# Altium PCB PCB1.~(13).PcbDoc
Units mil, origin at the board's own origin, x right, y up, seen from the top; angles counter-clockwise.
Board outline 6000 x 4000 mil, 2 copper layers (Top Layer, Bottom Layer); 3 components, 4 nets, 37 pads, 0 vias.
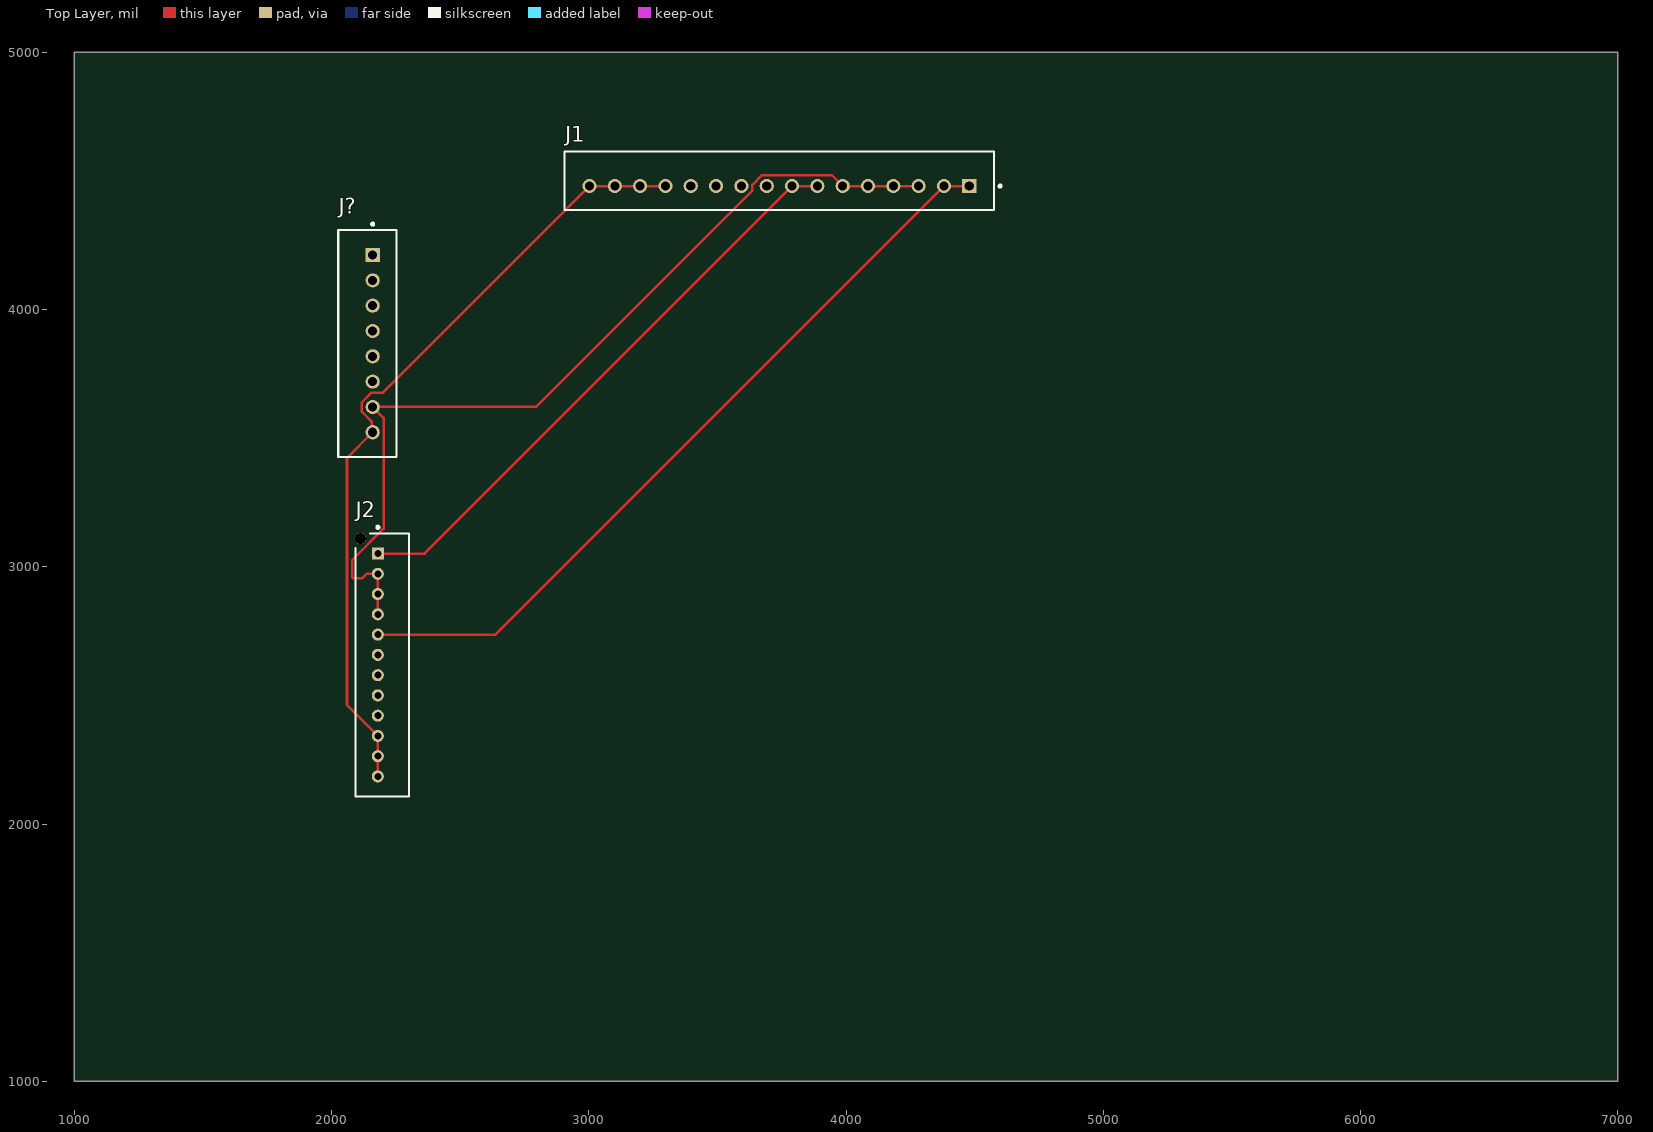
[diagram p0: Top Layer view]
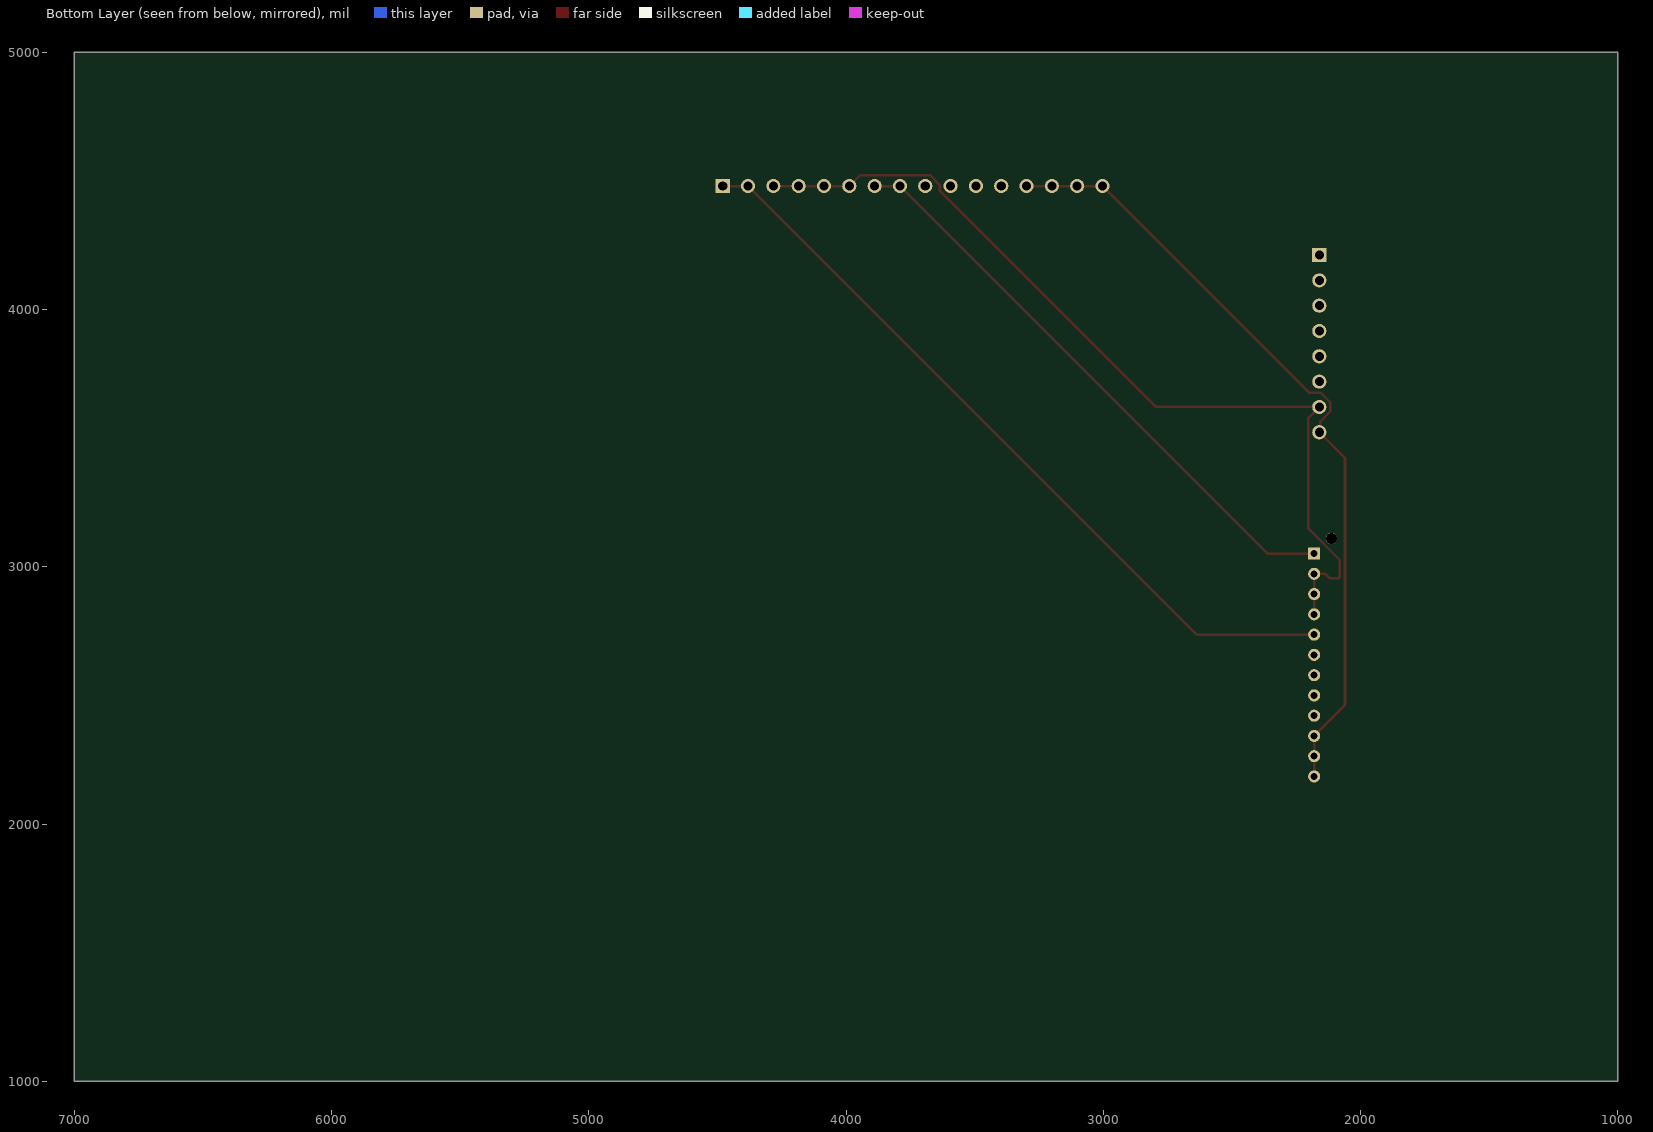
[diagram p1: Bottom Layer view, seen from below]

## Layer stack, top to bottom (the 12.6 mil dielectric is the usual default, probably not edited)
Top Solder: solder mask 0.4, Solder Resist, Dk 3.5
Top Layer: signal copper 1.4
Dielectric 1: dielectric 12.6, FR-4, Dk 4.8
Bottom Layer: signal copper 1.4
Bottom Solder: solder mask 0.4, Solder Resist, Dk 3.5

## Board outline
1000,1000 7000,1000 7000,5000 1000,5000

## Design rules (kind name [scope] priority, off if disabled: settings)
Clearance [All] p1: gap=10 ignorepadtopadclearanceinfootprint=FALSE
PolygonConnect [All] p1: connectstyle=Relief reliefconductorwidth=10 reliefentries=4 polygonreliefangle="90 Angle" airgapwidth=10
RoutingVias [All] p1: holewidth=28 width=50 viastyle="Through Hole" minholewidth=28 minwidth=50 maxholewidth=28 maxwidth=50
SolderMaskExpansion [All] p1: expansion=0 istentingtop=FALSE
SupplyNets "Schematic Supply Nets" [InNet('GND')] p1: voltage=0.000
Width [All] p1: maxlimit=10 minlimit=10 preferedwidth=10
30 further rules are at their usual default settings.

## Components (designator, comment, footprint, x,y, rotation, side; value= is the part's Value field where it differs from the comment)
J1 "B16B-XH-A(LF)(SN)" FP-B16B-XH-A_LF_SN-MFG 3741.06,4500.67 r0 top
J2 "B12B-PASK-1(LF)(SN)" FP-B12B-PASK-1_LF_SN-MFG 2197.72,2618.11 r90 top
J? "B8B-XH-A(LF)(SN)" FP-B8B-XH-A_LF_SN-MFG 2139.33,3867.36 r90 top

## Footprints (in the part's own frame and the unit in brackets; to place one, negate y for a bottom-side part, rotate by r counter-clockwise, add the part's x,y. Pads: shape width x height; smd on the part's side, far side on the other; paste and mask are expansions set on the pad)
FP-B8B-XH-A_LF_SN-MFG [mm]
  rect 1.4x1.4 hole 0.9 paste-2539.97 mask+0: 1(8.75,-0.525)
  round 1.4 hole 0.9 paste-2539.97 mask+0: 2(6.25,-0.525) 3(3.75,-0.525) 4(1.25,-0.525) 5(-1.25,-0.525) 6(-3.75,-0.525) 7(-6.25,-0.525) 8(-8.75,-0.525)
  silkscreen extent -11.2,-2.88 11.92,2.88, body extent -11.3,-2.98 11.3,2.98, height 0.25
FP-B12B-PASK-1_LF_SN-MFG [mm]
  rect 1.2x1.2 hole 0.7 paste-2539.97 mask+0: 1(11,0.45)
  round 1.2 hole 0.7 paste-2539.97 mask+0: 2(9,0.45) 3(7,0.45) 4(5,0.45) 5(3,0.45) 6(1,0.45) 7(-1,0.45) 8(-3,0.45) 9(-5,0.45) 10(-7,0.45) 11(-9,0.45) 12(-11,0.45)
  round 1.1 hole 1.1 unplated paste-2539.97 mask+0: ""(12.5,2.15)
  silkscreen extent -13,-2.65 13.72,2.65, body extent -13.1,-2.75 13.15,2.8, height 0.25
FP-B16B-XH-A_LF_SN-MFG [mm]
  rect 1.4x1.4 hole 0.9 paste-2539.97 mask+0: 1(18.75,-0.525)
  round 1.4 hole 0.9 paste-2539.97 mask+0: 2(16.25,-0.525) 3(13.75,-0.525) 4(11.25,-0.525) 5(8.75,-0.525) 6(6.25,-0.525) 7(3.75,-0.525) 8(1.25,-0.525) 9(-1.25,-0.525) 10(-3.75,-0.525) 11(-6.25,-0.525) 12(-8.75,-0.525) 13(-11.25,-0.525) 14(-13.75,-0.525) 15(-16.25,-0.525) 16(-18.75,-0.525)
  silkscreen extent -21.2,-2.88 21.93,2.88, body extent -21.3,-2.98 21.3,2.98, height 0.25

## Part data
J1: library part CMP-17439-000590-1, "CONN HEADER VERT 16POS 2.5MM", Color=Natural, Contact Resistance=20mR, Housing Color=White, Max Current Rating=3A, Max Operating Temperature=85°C, Max Voltage Rating (AC)=250V, Min Operating Temperature=-25°C, Package Quantity=200
J2: library part CMP-17439-000523-1, "CONN HEADER VERT 12POS 2MM", Color=Natural, Current Rating=3A, Flammability Rating="UL94 V-0", Housing Color=White, Voltage Rating=250V
J?: library part CMP-17438-000015-1, "CONN HEADER VERT 8POS 2.5MM", Color=Natural, Contact Resistance=20mR, Current Rating=3A, Housing Color=White, Insulation Resistance=1GR, Max Operating Temperature=85°C, Max Voltage Rating (AC)=250V, Min Operating Temperature=-25°C

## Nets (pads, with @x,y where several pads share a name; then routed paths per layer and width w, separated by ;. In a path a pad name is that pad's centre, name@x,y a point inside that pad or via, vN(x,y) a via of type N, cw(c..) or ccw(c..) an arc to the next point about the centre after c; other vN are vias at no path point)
GND: J1.13 J1.14 J1.15 J1.16 J2.10 J2.11 J2.12 J?.8 | length 3091.7
  Top Layer w10: J2.12 J2.11 J2.10 2060,2462.52 2060,3422.87 J?.8 2155.68,3527.2 2155.68,3565.43 2117.44,3603.67 2117.44,3638.93 2155.68,3677.17 2200.04,3677.17 J1.16 J1.15 J1.14 J1.13
NetJ1_1: J1.1 J1.2 J2.5 | length 3021.5
  Top Layer w10: J2.5 2637.05,2736.22 J1.2 J1.1
NetJ1_3: J1.3 J1.4 J1.5 J1.6 J2.2 J2.3 J2.4 J?.7 | length 3522.2
  Top Layer w10: J2.4 J2.3 J2.2 2136.61,2972.44 2119.17,2955 2085.86,2955 2080,2960.86 2080,3025.33 2202.56,3147.89 2202.56,3578.74 J?.7 2794.91,3621.3 3635.98,4462.37 3635.98,4484.32 3674.22,4522.56 3944.57,4522.56 J1.6 J1.5 J1.4 J1.3
NetJ1_7: J1.7 J1.8 J2.1 | length 2300.5
  Top Layer w10: J2.1 2361.46,3051.18 J1.8 J1.7
pads on no net: J1.9 J1.10 J1.11 J1.12 J2. J2.6 J2.7 J2.8 J2.9 J?.1 J?.2 J?.3 J?.4 J?.5 J?.6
